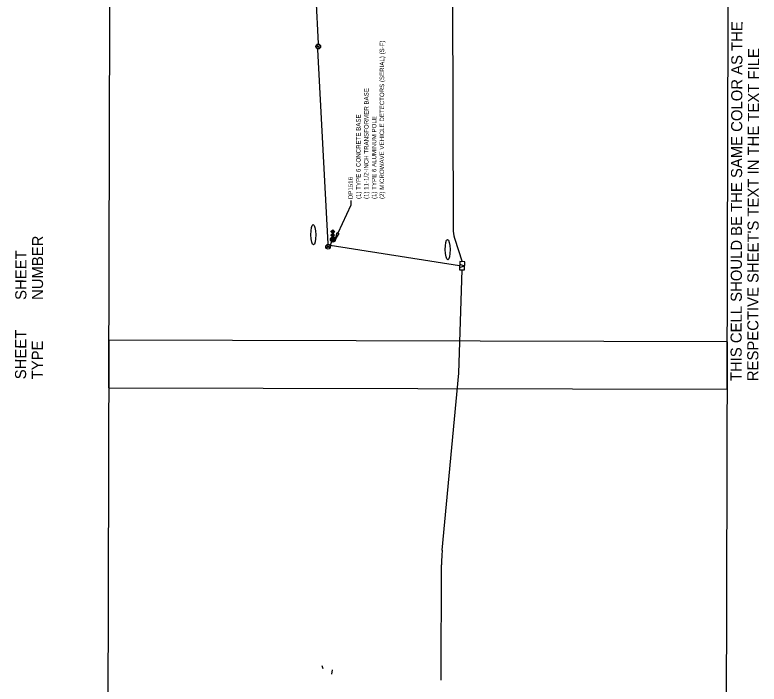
# Model space of a CAD drawing. Extents: x 601462 to 605493, y 331960 to 402715.
# Drawn here: x 602642 to 603815, y 375180 to 376234 of the extents above; entities that cross this region are included whole.
import ezdxf

# ---------------------------------------------------------------- set-up
doc = ezdxf.new("R2010")
doc.units = 0
for name, color, linetype in [('P_FTMS', 7, 'Continuous'), ('P_FTMSConduit', 7, 'Continuous'), ('P_MISC_TXT_1A (Construction)', 7, 'Continuous'), ('P_MISC_TXT_1B (Construction)', 7, 'Continuous')]:
    doc.layers.add(name, color=color, linetype=linetype)

# ---------------------------------------------------------------- blocks, each defined once
blk = doc.blocks.new('FTMS_FCV')
at = {"layer": 'P_FTMS'}
blk.add_line((12.7, 16.3), (0.6, -21.9), dxfattribs=at)
blk.add_lwpolyline([(39.1, 24.4), (-39.1, 24.4), (-39.1, -24.4), (39.1, -24.4)], close=True, dxfattribs=at)
blk.add_lwpolyline([(-12.1, 16.2), (0.6, -21.9)], dxfattribs=at)
blk = doc.blocks.new('_U231')
at = {"layer": 'P_FTMS'}
for p, q in [((12.1, 1.6), (-12.2, -0.1)), ((11.8, 3), (-12.1, 1.4)), ((11.9, 2.3), (-12.1, 0.6)), ((12.1, 0.8), (-12.1, -0.8)), ((12.1, 0.1), (-12.1, -1.6)), ((11.6, 3.7), (-12, 2.1)), ((-11.9, 2.5), (-11.4, -4.2)), ((11.3, 4.4), (-11.8, 2.9)), ((11, 5.2), (-11.6, 3.6)), ((10.6, 5.9), (-11.4, 4.4)), ((-11.3, 4.5), (-10.6, -6)), ((10.2, 6.6), (-11, 5.1)), ((9.8, 7.3), (-10.7, 5.9)), ((-10.7, 5.9), (-9.8, -7.2)), ((9.2, 8), (-10.2, 6.6)), ((-10, 6.9), (-9, -8.2)), ((8.6, 8.6), (-9.7, 7.4)), ((-9.3, 7.8), (-8.2, -9)), ((7.8, 9.3), (-9, 8.2)), ((-8.6, 8.5), (-7.4, -9.6)), ((6.9, 10), (-8.2, 9)), ((-8, 9.2), (-6.6, -10.2)), ((-7.3, 9.7), (-5.9, -10.6)), ((5.8, 10.7), (-7.2, 9.8)), ((-6.6, 10.3), (-5.1, -11)), ((4.5, 11.3), (-6, 10.6)), ((-5.9, 10.7), (-4.4, -11.4)), ((-5.1, 11), (-3.6, -11.6)), ((-4.4, 11.3), (-2.9, -11.8)), ((2.5, 11.9), (-4.1, 11.5)), ((-3.7, 11.6), (-2.1, -12)), ((-3, 11.8), (-1.4, -12.1)), ((-2.3, 12), (-0.6, -12.2)), ((-1.6, 12.1), (0.1, -12.2)), ((-0.8, 12.1), (0.8, -12.1)), ((-0.1, 12.2), (1.6, -12.1)), ((0.6, 12.1), (2.3, -11.9)), ((1.4, 12.1), (3, -11.8)), ((2.1, 12), (3.7, -11.6)), ((2.9, 11.8), (4.4, -11.3)), ((3.6, 11.6), (5.1, -11)), ((4.4, 11.3), (5.9, -10.7)), ((5.1, 11), (6.6, -10.2)), ((5.9, 10.6), (7.3, -9.8)), ((6.6, 10.2), (8, -9.2)), ((7.4, 9.7), (8.6, -8.6)), ((8.2, 9), (9.3, -7.8)), ((9, 8.2), (10, -6.9)), ((9.8, 7.2), (10.7, -5.8)), ((10.6, 5.9), (11.3, -4.5)), ((11.5, 4), (11.9, -2.5)), ((12.1, -0.6), (-12, -2.3)), ((12.1, -1.4), (-11.8, -3)), ((12, -2.1), (-11.6, -3.7)), ((11.8, -2.9), (-11.3, -4.4)), ((11.6, -3.6), (-11, -5.1)), ((11.3, -4.4), (-10.7, -5.9)), ((11.1, -5.1), (-10.2, -6.6)), ((10.6, -5.9), (-9.8, -7.3)), ((10.2, -6.6), (-9.2, -8)), ((9.6, -7.4), (-8.5, -8.6)), ((9, -8.2), (-7.8, -9.3)), ((8.2, -9), (-6.9, -10)), ((7.3, -9.8), (-5.8, -10.7)), ((6, -10.6), (-4.5, -11.3)), ((4.1, -11.5), (-2.6, -11.9))]:
    blk.add_line(p, q, dxfattribs=at)
blk.add_circle((0, 0), 12.2, dxfattribs=at)
blk = doc.blocks.new('FMD')
at = {"layer": 'P_FTMS'}
for p, q in [((16.9, 17.6), (-16.9, 17.6)), ((-16.1, 16.1), (-16.1, 18.4)), ((16.1, 16.1), (-16.1, 16.1)), ((15.5, 19), (-15.5, 19)), ((-14.6, 14.6), (-14.6, 19.9)), ((14.6, 14.6), (-14.6, 14.6)), ((14, 20.5), (-14, 20.5)), ((-13.2, 13.2), (-13.2, 21.3)), ((13.2, 13.2), (-13.2, 13.2)), ((12.5, 21.9), (-12.5, 21.9)), ((-11.7, 11.7), (-11.7, 22.8)), ((11.7, 11.7), (-11.7, 11.7)), ((11.1, 23.4), (-11.1, 23.4)), ((-10.2, 10.2), (-10.2, 24.2)), ((10.2, 10.2), (-10.2, 10.2)), ((9.6, 24.9), (-9.6, 24.9)), ((-8.8, 8.8), (-8.8, 25.7)), ((8.8, 8.8), (-8.8, 8.8)), ((8.2, 26.3), (-8.2, 26.3)), ((-7.3, 7.3), (-7.3, 27.2)), ((7.3, 7.3), (-7.3, 7.3)), ((6.7, 27.8), (-6.7, 27.8)), ((-5.9, 5.9), (-5.9, 28.6)), ((5.9, 5.9), (-5.9, 5.9)), ((5.2, 29.3), (-5.2, 29.3)), ((-4.4, 4.4), (-4.4, 30.1)), ((4.4, 4.4), (-4.4, 4.4)), ((3.8, 30.7), (-3.8, 30.7)), ((-2.9, 2.9), (-2.9, 31.6)), ((2.9, 2.9), (-2.9, 2.9)), ((2.3, 32.2), (-2.3, 32.2)), ((-1.5, 1.5), (-1.5, 33)), ((1.5, 1.5), (-1.5, 1.5)), ((0.8, 33.6), (-0.8, 33.6)), ((0, 0), (0, 34.5)), ((1.5, 1.5), (1.5, 33)), ((2.9, 2.9), (2.9, 31.6)), ((4.4, 4.4), (4.4, 30.1)), ((5.9, 5.9), (5.9, 28.6)), ((7.3, 7.3), (7.3, 27.2)), ((8.8, 8.8), (8.8, 25.7)), ((10.2, 10.2), (10.2, 24.2)), ((11.7, 11.7), (11.7, 22.8)), ((13.2, 13.2), (13.2, 21.3)), ((14.6, 14.6), (14.6, 19.9)), ((16.1, 16.1), (16.1, 18.4))]:
    blk.add_line(p, q, dxfattribs=at)
blk.add_lwpolyline([(-17.2, 17.2), (0, 34.5), (17.2, 17.2), (0, 0)], close=True, dxfattribs=at)

msp = doc.modelspace()

# ---------------------------------------------------------------- linework, layer by layer
at = {"layer": 'P_FTMS'}
msp.add_line((603142.5, 375202.7), (603141.5, 375195.8), dxfattribs=at)
for centre in [(603120.4, 376184.6), (603136, 375869.2)]:
    msp.add_circle(centre, 3.75, dxfattribs=at)
for centre, start, end in [((603120, 376180.1), 32.6299, 138.8855), ((603120.7, 376189.1), 212.6299, 318.8855), ((603135.7, 375864.7), 32.6299, 138.8855), ((603136.3, 375873.6), 212.6299, 318.8855)]:
    msp.add_arc(centre, 3.75, start, end, dxfattribs=at)
for centre in [(603112.7, 375888), (603324.4, 375864.7)]:
    msp.add_ellipse(centre, major_axis=(-0.4, 16), ratio=0.23471, dxfattribs=at)
at = {"layer": 'P_FTMSConduit'}
for p, q in [((603329.3, 377421.4), (603332.9, 375897.8)), ((603120.7, 376189.1), (603106.3, 376480.5)), ((603136.3, 375873.6), (603120, 376180.1)), ((603141.6, 375877.2), (603139.1, 375871.2)), ((603335.4, 375882.5), (603347.3, 375845.6)), ((603343.2, 375839.3), (603139.1, 375871.2)), ((603342.2, 375669.8), (603347.1, 375832.8)), ((603315.9, 375391.2), (603342.2, 375669.8)), ((603314.3, 375186.6), (603314.7, 375368.2)), ((603128.1, 375204.3), (603126.6, 375208.8))]:
    msp.add_line(p, q, dxfattribs=at)
for points in [[(603151.6, 375890.9), (603172.2, 375935.2)], [(603172.2, 375935.2), (603172.2, 375942.2)]]:
    msp.add_lwpolyline(points, dxfattribs=at)
msp.add_lwpolyline([(603153.1, 375890.2), (603147.4, 375881.8), (603150.1, 375891.6)], close=True, dxfattribs=at)
for centre, radius, start, end in [((603382.9, 375897.9), 50, 180.1357, 197.9715), ((603564.7, 375367.6), 250, 174.588, 179.8526)]:
    msp.add_arc(centre, radius, start, end, dxfattribs=at)
at = {"layer": 'P_MISC_TXT_1A (Construction)'}
msp.add_lwpolyline([(603765, 375644.6), (603769, 377219.6), (602794, 377222.1), (602790, 375647.1)], close=True, dxfattribs=at)
msp.add_lwpolyline([(603765, 375644.6), (603769, 377219.6), (602794, 377222.1), (602790, 375647.1)], close=True, dxfattribs=at)
at = {"layer": 'P_MISC_TXT_1B (Construction)'}
msp.add_lwpolyline([(603761.1, 374144.6), (603765.2, 375719.6), (602790.2, 375722.1), (602786.1, 374147.1)], close=True, dxfattribs=at)
msp.add_lwpolyline([(603761.1, 374144.6), (603765.2, 375719.6), (602790.2, 375722.1), (602786.1, 374147.1)], close=True, dxfattribs=at)

# ---------------------------------------------------------------- block references
at = {"layer": 'P_FTMS'}
for name, p, xscale, yscale, rotation in [('FMD', (603140.5, 375893.1), 0.1640416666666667, 0.16404166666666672, -91.54665377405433), ('_U231', (603143.6, 375880.6), 0.32808333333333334, 0.32808333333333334, 2.5604819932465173), ('FMD', (603140.4, 375887.5), 0.1640416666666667, 0.16404166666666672, -91.54665377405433), ('FTMS_FCV', (603347.2, 375839.2), 0.16404166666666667, 0.16404166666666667, 88.76248754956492)]:
    msp.add_blockref(name, p, dxfattribs=dict(at, xscale=xscale, yscale=yscale, rotation=rotation))

# ---------------------------------------------------------------- texts
at = {"layer": 'P_FTMSConduit'}
for s, p in [('(2) MICROWAVE VEHICLE DETECTORS (SERIAL) (S-F)', (603224.2, 375944.4)), ('(1) 11-1/2-INCH TRANSFORMER BASE', (603199.6, 375944.4)), ('(1) TYPE 6 CONCRETE BASE', (603187.1, 375944.4)), ('(1) TYPE 6 ALUMINUM POLE', (603211.9, 375944.4)), ('DP1516', (603174.8, 375944.2))]:
    msp.add_text(s, height=7, rotation=89.9604, dxfattribs=at).set_placement(p)
at = {"layer": 'P_MISC_TXT_1A (Construction)'}
for s, p in [('THIS CELL SHOULD BE THE SAME COLOR AS THE', (603787.6, 375657.5)), ('THIS CELL SHOULD BE THE SAME COLOR AS THE', (603787.6, 375657.5)), ("RESPECTIVE SHEET'S TEXT IN THE TEXT FILE", (603813.9, 375657.4)), ("RESPECTIVE SHEET'S TEXT IN THE TEXT FILE", (603813.9, 375657.4)), ('NUMBER', (602686.7, 375785.3)), ('NUMBER', (602686.7, 375785.3)), ('SHEET', (602660.5, 375785.4)), ('SHEET', (602660.5, 375785.4)), ('SHEET', (602660.1, 375660.4)), ('SHEET', (602660.1, 375660.4)), ('TYPE', (602686.4, 375660.3)), ('TYPE', (602686.4, 375660.3))]:
    msp.add_text(s, height=17.5, rotation=89.8526, dxfattribs=at).set_placement(p)

doc.saveas('drawing.dxf')
